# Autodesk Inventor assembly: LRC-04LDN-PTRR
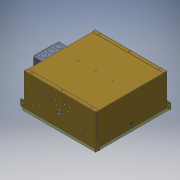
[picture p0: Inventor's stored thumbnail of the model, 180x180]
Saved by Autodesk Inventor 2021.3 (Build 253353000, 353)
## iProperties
load_classification: Lighting
motor: 0 ul
Part Number: LRC-04LDN-PTRR
Document SubType Name: Assembly
Designer: JChurch
description: 0:0:Regressed Lens 4" Downlight - COB LED
manufacturer: 0:0:The Kirlin Company
model: 0:0:LRC-04LDN
url: 0:0:
Author: JChurch
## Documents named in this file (6)
- X:\Revit Files\0000-Un-Zipped\COB\LRC-04LDN-PTR\LRC-04LDN-PTRR.iam
- X:\INVENTOR\830\830520-00-00.ipt
- X:\INVENTOR\881\881088-00-00.iam
- X:\INVENTOR\750\750472-00-00.iam
- X:\INVENTOR\725\725383-01-00.ipt
- X:\Revit Files\0000-Un-Zipped\COB\LRC-04LDN-PTR\LRC-04LDN-PTRR_Substitute_1.ipt
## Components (5 placed, 5 different names)
1. 830520-00-00:1 — Mate:1, Mate:2, Mate:3, Mate:4, Tangent:1, Angle:1, Insert:2
2. 881088-00-00:1 [sub-assembly] — Mate:4, Tangent:1, Angle:1
3. 750472-00-00:1 [sub-assembly] — Insert:1, Insert:2
4. 725383-01-00:1 — Insert:1
5. LRC-04LDN-PTRR_Substitute_1:1
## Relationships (8: Mate 4, Insert 2, Tangent 1, Angle 1)
- Mate:1: 830520-00-00:1
- Mate:2: 830520-00-00:1
- Mate:3: 830520-00-00:1
- Mate:4: 830520-00-00:1 ↔ 881088-00-00:1
- Tangent:1: 830520-00-00:1 ↔ 881088-00-00:1
- Angle:1: 830520-00-00:1 ↔ 881088-00-00:1
- Insert:1: 750472-00-00:1 ↔ 725383-01-00:1
- Insert:2: 830520-00-00:1 ↔ 750472-00-00:1
